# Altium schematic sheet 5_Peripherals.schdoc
size 309 x 223 mm; Symbol: Sheet-Symbol_A4; Device: Sheet-Symbol_A4; @Project Name: ODrive Rev Motor Module; @Page Count: 5; @Update Date: 2024-10-18; @Create Date: 2024-10-10; @Schematic Name: Schematic-A; @Page No: 5; @Page Name: Peripherals; Company: UA Nasa Robotics; Reviewed: None; Version: 1.0; Page Size: A4; Part Number: AA; Drawn: Eli B; @Board Name: BaseModule; @Create Time: 23:03:32; @Update Time: 20:57:32
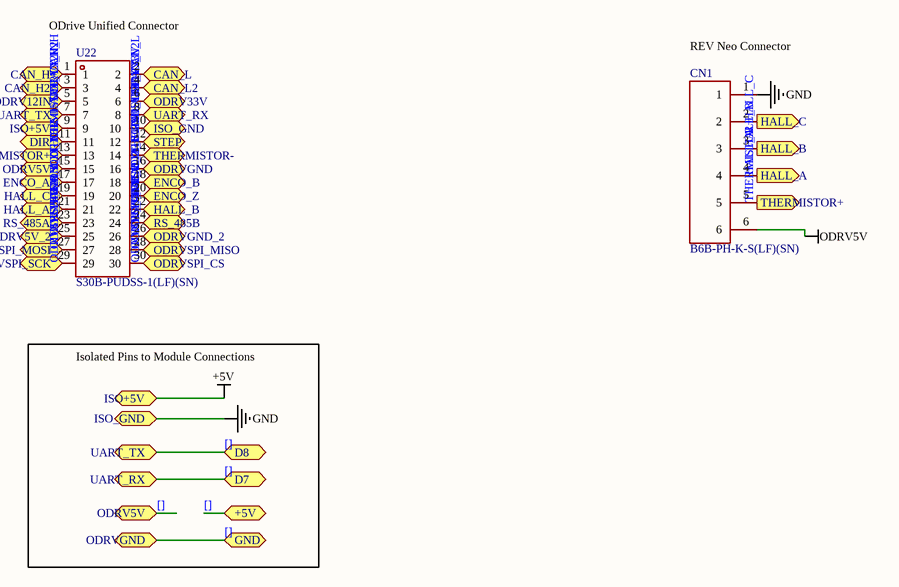
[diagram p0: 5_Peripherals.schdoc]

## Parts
CN1  B6B-PH-K-S(LF)(SN)  [CONN-TH_B6B-PH-K-S]  (value not drawn)
U22  S30B-PUDSS-1(LF)(SN)  [CONN-TH_S30B-PUDSS-1]  (value not drawn)

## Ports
+5V (bidir), CAN_H2 (bidir), CAN_H (bidir), CAN_L2 (bidir), CAN_L (bidir), D7 (bidir), D8 (bidir), DIR (bidir), ENCO_A (bidir), ENCO_B (bidir), ENCO_Z (bidir), GND (bidir), HALL_A (bidir), HALL_A (out), HALL_B (bidir), HALL_B (out), HALL_C (bidir), HALL_C (out), ISO+5V (bidir), ISO_GND (bidir), ODRV5V (bidir), ODRV5V_2 (bidir), ODRV12IN (bidir), ODRV33V (bidir), ODRVGND (bidir), ODRVGND_2 (bidir), ODRVSPI_CS (bidir), ODRVSPI_MISO (bidir), ODRVSPI_MOSI (bidir), ODRVSPI_SCK (bidir), RS_485A (bidir), RS_485B (bidir), STEP (bidir), THERMISTOR+ (bidir), THERMISTOR+ (out), THERMISTOR- (bidir), UART_RX (bidir), UART_TX (bidir)

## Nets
[]: CN1.6 U22.7 U22.8 U22.15 U22.16 ; port UART_RX, port ODRVGND, port ODRV5V, port UART_TX, port D8, port D7, port +5V, port GND  [also labelled ODRV5V, ODRVGND, UART_RX, UART_TX]
ISO+5V: U22.9 ; port ISO+5V  [also labelled +5V]
ISO_GND: CN1.1 U22.10 ; port ISO_GND  [also labelled GND]
CAN_H: U22.1 ; port CAN_H
CAN_H2: U22.3 ; port CAN_H2
CAN_L: U22.2 ; port CAN_L
CAN_L2: U22.4 ; port CAN_L2
DIR: U22.11 ; port DIR
ENCO_A: U22.17 ; port ENCO_A
ENCO_B: U22.18 ; port ENCO_B
ENCO_Z: U22.20 ; port ENCO_Z
HALL_A: CN1.4 U22.21 ; port HALL_A
HALL_B: CN1.3 U22.22 ; port HALL_B
HALL_C: CN1.2 U22.19 ; port HALL_C
ODRV5V_2: U22.25 ; port ODRV5V_2
ODRV12IN: U22.5 ; port ODRV12IN
ODRV33V: U22.6 ; port ODRV33V
ODRVGND_2: U22.26 ; port ODRVGND_2
ODRVSPI_CS: U22.30 ; port ODRVSPI_CS
ODRVSPI_MISO: U22.28 ; port ODRVSPI_MISO
ODRVSPI_MOSI: U22.27 ; port ODRVSPI_MOSI
ODRVSPI_SCK: U22.29 ; port ODRVSPI_SCK
RS_485A: U22.23 ; port RS_485A
RS_485B: U22.24 ; port RS_485B
STEP: U22.12 ; port STEP
THERMISTOR+: CN1.5 U22.13 ; port THERMISTOR+
THERMISTOR-: U22.14 ; port THERMISTOR-

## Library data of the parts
CN1 = B6B-PH-K-S(LF)(SN)_C131342: Pins Structure:1x6P Pitch:2mm Mounting Style:Straight Reference Series:PH Number of Pins:6P Number of Rows:1 Number of PINs Per Row:6 Row Spacing:- Current Rating (Max):2A Contact Material:Brass Contact Plating:Tin Operating Temperature Range:-25℃~+85℃ Op; Manufacturer: JST; Add into BOM: yes; Pins Structure: 1x6P; Pitch: 2mm; Reference Series: PH; Number of PINs Per Row: 6; Current Rating (Max): 2A; Rated Voltage (Max): 100V; Plastic Material: PA66; Flame Retardant Rating: UL94V-0; Supplementary Features: 打K脚; Z-Height of the Board: 6mm; X-Length of Bottom Edge on Board (Spacing Line): 13.9mm; Y-Width of Bottom Edge on Board: 4.5mm
U22 = S30B-PUDSS-1(LF)(SN): Pins Structure:2x15P Pitch:2mm Mounting Style:Bend insert Reference Series:PUD Number of Pins:30P Number of Rows:2 Number of PINs Per Row:15 Row Spacing:2mm Current Rating (Max):3A Contact Material:Copper Alloy Contact Plating:Tin Operating Temperature Ra; Manufacturer: JST; Add into BOM: yes; Pins Structure: 2x15P; Pitch: 2mm; Reference Series: PUD; Number of PINs Per Row: 15; Current Rating (Max): 3A; Rated Voltage (Max): 250V; Plastic Material: Glass Fiber Reinforced PA66; Flame Retardant Rating: UL94V-0; Supplementary Features: With column; Z-Height of the Board: 8.5mm; X-Length of Bottom Edge on Board (Spacing Line): 32mm; Y-Width of Bottom Edge on Board: 12.7mm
